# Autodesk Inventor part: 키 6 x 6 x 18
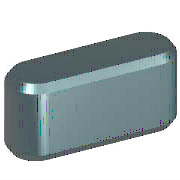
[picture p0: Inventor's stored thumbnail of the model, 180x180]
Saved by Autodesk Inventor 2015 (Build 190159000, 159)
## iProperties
IsCustomPart: 1
Created: 2012-02
Part Number: 키 6 x 6 x 18
Material: 강철, 연강
Description: 키 및 해당 키홈
Document SubType Name: Modeling
Standard: KS B 1311
Designer: mduedu
Standards Organization: KS
Language: ko-KR
Size Designation: 6 x 6 x 18
Categories: <MemberInstance><Categories><Category DisplayName="샤프트 부품" InternalName="7f7aeb1f-a693-4053-b835-cee3144e0d98" Mnemonic="SHFT"><Category DisplayName="키" Interna
Density: 1 g/cm^3
Appearance: 노란색
Author: mduedu
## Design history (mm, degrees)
workplane "Work Plane1"
workplane "Work Plane2"
sketch "스케치1"
  geometry: L1 (3, 3)-(15, 3); L2 (15, -3)-(3, -3); L3 (0, 9.4)-(0, -7.4) reference; L4 (-5, 0)-(30, 0) reference; L5 (18, 0)-(18, 7); A1 r 3 centre (3, 0) between (3, 3) and (3, -3); A2 r 3 centre (15, 0) between (15, -3) and (15, 3)
  constraints: 6 end point, 5 point on circle, 4 tangent, 3 point on line, 2 centre point, 1 horizontal, 1 parallel, 1 perpendicular
  dimensions: "d0" = 3 radius of A1 (= 0.5 x PB); "d13" = 3 radius of A2 (= 0.5 x PB); "d14" = 18 distance between parallel lines of L5 L3 (= NLG)
extrude "본체1" new body sketch "스케치1" taper "d3" = 0 deg; stored distance "d4" = 10
workplane "Work Plane3"
body "Solid1"
chamfer "모따기1" distance "d8" = 0.4 (= PHH); stored, may be unused: second distance "d9" = 0.4 (= PHH), angle "d15" = 45 deg
other parameters: "d1" = -3.5 (= -PNT), "d2" = 2.5 (= PH - PNT), "NLG" = 18 [user parameter; used in 3 equation terms], "PB" = 6 [user parameter; used in 2 equation terms], "PNT" = 3.5 [user parameter; used in 2 equation terms], "PH" = 6 [user parameter; used in 1 equation term], "PHH" = 0.4 [user parameter; used in 2 equation terms], "d10" = 0, "d16" = 0, "d17" = 0, "d18" = 0, "WDMIN" = 17 [user parameter], "PLB2" = 18 (= NLG) [user parameter], "WDMAX" = 22 [user parameter], "PLB1" = 18 (= NLG) [user parameter], "RR" = 0.16 [user parameter], "PUEB" = 2.8 [user parameter]
